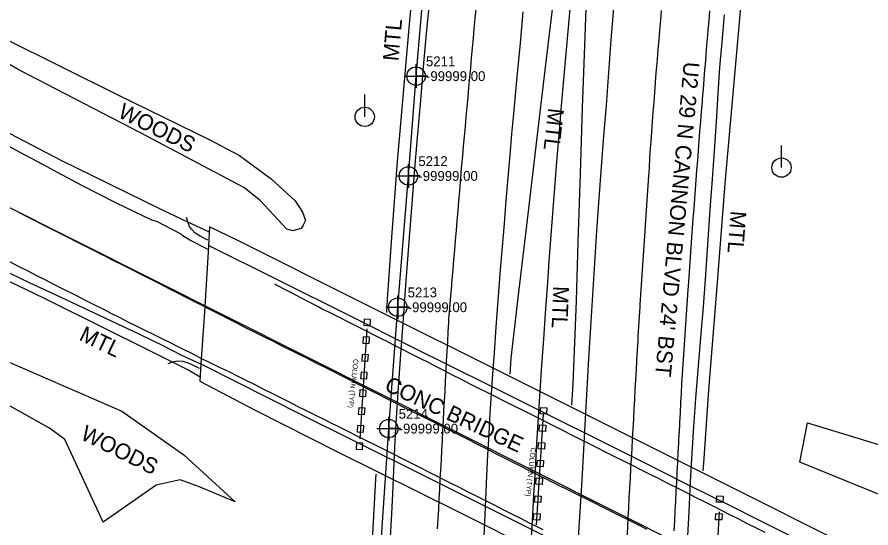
# Model space of a CAD drawing. Extents: x 1516784 to 1522736, y 634838 to 639369.
# Drawn here: x 1520333.6 to 1520550, y 638106.7 to 638236.3 of the extents above; entities that cross this region are included whole.
import ezdxf

# ---------------------------------------------------------------- set-up
doc = ezdxf.new("R2010")
doc.units = 0
for name, color, linetype in [('COGO Default Point Elevation', 7, 'Continuous'), ('COGO Default Point Number', 7, 'Continuous'), ('Exist Environmental Wetland Boundary Cogo Number', 7, 'Continuous'), ('Exist Environmental Wetland Boundary Text', 7, 'Continuous'), ('Exist Guardrail', 7, 'Continuous'), ('Exist Guardrail Text', 7, 'Continuous'), ('Exist Hydro Jurisdictional Stream or Body of Water NEU Mitigable', 7, 'Continuous'), ('Exist Hydro Swamp or Marsh Text', 7, 'Continuous'), ('Exist Roads EOT Text', 7, 'Continuous'), ('Exist Structure Major Deck Tunnel Box Culvert Text', 7, 'Continuous'), ('Exist Utilities Gas UG Line SUE LOS B', 7, 'Continuous'), ('Exist Utilities Gas UG Line SUE LOS B Cogo Elevation', 7, 'Continuous'), ('Exist Utilities Gas UG Line SUE LOS B Cogo Number', 7, 'Continuous'), ('Exist Utilities Gas UG Line SUE LOS B Cogo Point CELL', 7, 'Continuous'), ('Exist Utilities Power Pole CELL', 7, 'Continuous'), ('Exist Vegetation Woods Line', 7, 'Continuous'), ('Exist Vegetation Woods Line Text', 7, 'Continuous'), ('Scratch_Level_5', 7, 'Continuous')]:
    doc.layers.add(name, color=color, linetype=linetype)

msp = doc.modelspace()

# ---------------------------------------------------------------- linework, layer by layer
at = {"layer": 'COGO Default Point Elevation'}
for points in [[(1520449.83, 638238.35), (1520449.6, 638235.86), (1520449.38, 638233.37), (1520449.15, 638230.88), (1520448.92, 638228.39), (1520448.7, 638225.9), (1520448.47, 638223.42), (1520448.24, 638220.93), (1520448.02, 638218.44), (1520447.79, 638215.95), (1520447.56, 638213.46), (1520447.34, 638210.97), (1520447.11, 638208.49), (1520446.88, 638206), (1520446.66, 638203.51), (1520446.43, 638201.02), (1520446.37, 638200.42), (1520446.16, 638197.93), (1520445.95, 638195.44), (1520445.88, 638194.61), (1520445.67, 638192.12), (1520445.46, 638189.63), (1520445.26, 638187.14), (1520445.05, 638184.65), (1520444.84, 638182.16), (1520444.63, 638179.67), (1520444.42, 638177.18), (1520444.21, 638174.69), (1520444.01, 638172.21), (1520443.8, 638169.72), (1520443.59, 638167.23), (1520443.38, 638164.74), (1520443.17, 638162.25), (1520442.96, 638159.76), (1520442.89, 638158.92), (1520442.76, 638156.43), (1520442.63, 638153.93), (1520442.49, 638151.44), (1520442.36, 638148.94), (1520442.22, 638146.45), (1520442.09, 638143.96), (1520441.95, 638141.46), (1520441.82, 638138.97), (1520441.69, 638136.47), (1520441.55, 638133.98), (1520441.42, 638131.48), (1520441.28, 638128.99), (1520441.15, 638126.49), (1520441.02, 638124), (1520440.88, 638121.5), (1520440.75, 638119.01), (1520440.61, 638116.51), (1520440.48, 638114.02), (1520440.35, 638111.52), (1520440.21, 638109.03), (1520440.08, 638106.53)], [(1520488.18, 638104.39), (1520488.32, 638106.88), (1520488.45, 638109.38), (1520488.59, 638111.87), (1520488.73, 638114.37), (1520488.87, 638116.86), (1520489.01, 638119.35), (1520489.15, 638121.85), (1520489.28, 638124.34), (1520489.42, 638126.84), (1520489.56, 638129.33), (1520489.7, 638131.83), (1520489.84, 638134.32), (1520489.98, 638136.82), (1520490.11, 638139.31), (1520490.25, 638141.81), (1520490.39, 638144.3), (1520490.53, 638146.8), (1520490.67, 638149.29), (1520490.81, 638151.79), (1520490.94, 638154.28), (1520491, 638155.35), (1520491.16, 638157.84), (1520491.32, 638160.33), (1520491.48, 638162.83), (1520491.52, 638163.37), (1520491.68, 638165.86), (1520491.84, 638168.35), (1520492, 638170.84), (1520492.16, 638173.34), (1520492.32, 638175.83), (1520492.48, 638178.32), (1520492.64, 638180.82), (1520492.8, 638183.31), (1520492.81, 638183.51), (1520492.98, 638186.01), (1520493.15, 638188.5), (1520493.32, 638190.99), (1520493.49, 638193.48), (1520493.66, 638195.97), (1520493.81, 638198.05), (1520493.97, 638200.54), (1520494.14, 638203.04), (1520494.25, 638204.71), (1520494.44, 638207.2), (1520494.63, 638209.69), (1520494.82, 638212.19), (1520495.01, 638214.68), (1520495.2, 638217.17), (1520495.39, 638219.66), (1520495.58, 638222.15), (1520495.77, 638224.64), (1520495.84, 638225.5), (1520496.05, 638227.99), (1520496.27, 638230.48), (1520496.49, 638232.97), (1520496.7, 638235.46), (1520496.92, 638237.95)], [(1520500.14, 638106.03), (1520500.26, 638108.53), (1520500.38, 638111.02), (1520500.51, 638113.52), (1520500.62, 638115.86), (1520500.75, 638118.35), (1520500.88, 638120.85), (1520501.01, 638123.34), (1520501.14, 638125.84), (1520501.27, 638128.33), (1520501.4, 638130.83), (1520501.41, 638130.93), (1520501.54, 638133.43), (1520501.68, 638135.92), (1520501.82, 638138.42), (1520501.96, 638140.91), (1520502.08, 638143.25), (1520502.24, 638145.74), (1520502.4, 638148.24), (1520502.57, 638150.73), (1520502.73, 638153.22), (1520502.89, 638155.72), (1520502.98, 638157.12), (1520503.15, 638159.62), (1520503.32, 638162.11), (1520503.49, 638164.6), (1520503.66, 638167.09), (1520503.8, 638169.16), (1520503.97, 638171.65), (1520504.15, 638174.14), (1520504.32, 638176.63), (1520504.5, 638179.12), (1520504.67, 638181.62), (1520504.75, 638182.66), (1520504.94, 638185.16), (1520505.13, 638187.65), (1520505.32, 638190.14), (1520505.51, 638192.63), (1520505.69, 638194.93), (1520505.88, 638197.42), (1520506.06, 638199.91), (1520506.25, 638202.4), (1520506.44, 638204.83), (1520506.64, 638207.32), (1520506.84, 638209.81), (1520507.04, 638212.3), (1520507.24, 638214.79), (1520507.3, 638215.51), (1520507.5, 638218), (1520507.7, 638220.49), (1520507.91, 638222.98), (1520508, 638224.16), (1520508.21, 638226.65), (1520508.41, 638229.14), (1520508.62, 638231.63), (1520508.72, 638232.83), (1520508.94, 638235.32), (1520509.17, 638237.81)], [(1520381.04, 638162.84), (1520378.81, 638163.98), (1520376.59, 638165.12), (1520374.36, 638166.26), (1520372.14, 638167.4), (1520369.91, 638168.54), (1520368.97, 638169.02), (1520366.74, 638170.14), (1520364.51, 638171.27), (1520362.28, 638172.39), (1520360.05, 638173.52), (1520357.82, 638174.65), (1520355.58, 638175.77), (1520355.32, 638175.9), (1520353.09, 638177.04), (1520350.86, 638178.17), (1520348.63, 638179.3), (1520346.41, 638180.43), (1520344.18, 638181.56), (1520342.51, 638182.41), (1520340.28, 638183.54), (1520338.05, 638184.68), (1520335.83, 638185.81), (1520333.6, 638186.95)], [(1520331.66, 638174.25), (1520333.89, 638173.13), (1520334.09, 638173.02), (1520336.32, 638171.89), (1520338.55, 638170.76), (1520340.78, 638169.63), (1520343, 638168.49), (1520345.23, 638167.36), (1520347.46, 638166.23), (1520348.62, 638165.64), (1520350.85, 638164.51), (1520353.08, 638163.38), (1520355.31, 638162.26), (1520357.55, 638161.13), (1520359.78, 638160), (1520361.51, 638159.12), (1520363.75, 638158.01), (1520365.99, 638156.9), (1520368.23, 638155.79), (1520370.47, 638154.67), (1520372.71, 638153.56), (1520373.46, 638153.18), (1520375.7, 638152.06), (1520377.93, 638150.94), (1520379.97, 638149.9), (1520380.2, 638149.79)], [(1520398.79, 638168.61), (1520401.01, 638167.47), (1520403.23, 638166.32), (1520405.45, 638165.17), (1520407.67, 638164.02), (1520409.89, 638162.87), (1520410.95, 638162.32), (1520413.18, 638161.19), (1520415.41, 638160.06), (1520417.64, 638158.94), (1520419.87, 638157.81), (1520422.1, 638156.68), (1520424.33, 638155.55), (1520426.56, 638154.42), (1520426.76, 638154.32), (1520428.98, 638153.18), (1520431.21, 638152.05), (1520433.44, 638150.91), (1520435.67, 638149.78), (1520437.9, 638148.65), (1520439.25, 638147.96), (1520441.47, 638146.81), (1520443.69, 638145.67), (1520445.92, 638144.52), (1520448.14, 638143.38), (1520450.36, 638142.24), (1520452.6, 638141.13), (1520454.84, 638140.03), (1520457.08, 638138.92), (1520459.32, 638137.81), (1520461.56, 638136.71), (1520462.93, 638136.03), (1520465.16, 638134.9), (1520467.38, 638133.77), (1520469.61, 638132.64), (1520471.84, 638131.51), (1520474.07, 638130.38), (1520476.3, 638129.24), (1520478.3, 638128.23), (1520480.54, 638127.11), (1520482.77, 638125.98), (1520485.01, 638124.86), (1520487.24, 638123.74), (1520489.48, 638122.62), (1520491.71, 638121.5), (1520493.94, 638120.38), (1520496.18, 638119.26), (1520498.41, 638118.13), (1520498.77, 638117.96), (1520501, 638116.83), (1520503.23, 638115.7), (1520505.46, 638114.57), (1520507.69, 638113.44), (1520509.92, 638112.31), (1520512.15, 638111.18), (1520514.16, 638110.16), (1520516.39, 638109.03), (1520518.62, 638107.9), (1520520.86, 638106.77), (1520523.09, 638105.65)], [(1520493.23, 638106.38), (1520491, 638107.5), (1520488.76, 638108.62), (1520486.53, 638109.74), (1520484.29, 638110.86), (1520482.09, 638111.96), (1520479.85, 638113.08), (1520477.61, 638114.19), (1520475.38, 638115.3), (1520473.14, 638116.41), (1520470.9, 638117.53), (1520468.66, 638118.64), (1520467.9, 638119.02), (1520465.66, 638120.14), (1520463.42, 638121.25), (1520461.19, 638122.37), (1520458.95, 638123.49), (1520457.15, 638124.4), (1520454.92, 638125.54), (1520452.7, 638126.68), (1520450.47, 638127.82), (1520448.25, 638128.96), (1520446.02, 638130.1), (1520444.49, 638130.88), (1520442.26, 638131.99), (1520440.02, 638133.11), (1520437.78, 638134.22), (1520435.54, 638135.33), (1520433.3, 638136.44), (1520431.73, 638137.22), (1520429.51, 638138.35), (1520427.28, 638139.49), (1520425.05, 638140.62), (1520422.82, 638141.76), (1520420.6, 638142.89), (1520418.37, 638144.03), (1520418.19, 638144.12), (1520415.95, 638145.25), (1520413.72, 638146.37), (1520411.49, 638147.5), (1520409.26, 638148.62), (1520407.02, 638149.75), (1520405.26, 638150.64), (1520403.02, 638151.75), (1520400.78, 638152.86), (1520398.54, 638153.97), (1520396.3, 638155.08), (1520394.06, 638156.19), (1520393.9, 638156.27), (1520391.67, 638157.41), (1520389.45, 638158.55), (1520387.22, 638159.68), (1520384.99, 638160.82), (1520382.77, 638161.95), (1520381.92, 638162.39), (1520381.37, 638162.67)], [(1520380.33, 638149.73), (1520382.58, 638148.64), (1520384.83, 638147.54), (1520387.08, 638146.45), (1520389.37, 638145.33), (1520391.6, 638144.21), (1520393.83, 638143.08), (1520396.07, 638141.96), (1520398.3, 638140.83), (1520400.53, 638139.7), (1520402.54, 638138.69), (1520404.77, 638137.57), (1520407, 638136.45), (1520409.24, 638135.33), (1520411.47, 638134.21), (1520412.95, 638133.47), (1520415.19, 638132.36), (1520417.43, 638131.24), (1520419.67, 638130.13), (1520421.91, 638129.02), (1520424.15, 638127.91), (1520426.39, 638126.8), (1520426.68, 638126.65), (1520428.91, 638125.52), (1520431.14, 638124.39), (1520433.37, 638123.25), (1520435.6, 638122.12), (1520437.83, 638120.99), (1520440.06, 638119.86), (1520441.31, 638119.22), (1520443.54, 638118.09), (1520445.77, 638116.97), (1520448, 638115.84), (1520450.23, 638114.71), (1520452.47, 638113.59), (1520454.45, 638112.59), (1520456.68, 638111.46), (1520458.91, 638110.33), (1520461.14, 638109.2), (1520463.37, 638108.08), (1520465.6, 638106.95), (1520466.79, 638106.35)]]:
    msp.add_lwpolyline(points, dxfattribs=at)
at = {"layer": 'COGO Default Point Number'}
for points in [[(1520438.23, 638241.19), (1520437.37, 638233.01), (1520436.59, 638224.54), (1520435.8, 638215.21), (1520434.97, 638205.7), (1520434.29, 638197.75), (1520433.59, 638189.02), (1520432.85, 638179.26), (1520432.13, 638169.41), (1520431.45, 638159.85), (1520430.79, 638150.79), (1520430.09, 638141.17), (1520429.74, 638135.92), (1520429.41, 638130.44), (1520429.16, 638125.27), (1520428.74, 638115.49), (1520428.46, 638110.31), (1520428.17, 638104.52)], [(1520475.78, 638102.87), (1520476.3, 638110.91), (1520476.78, 638118.82), (1520477.22, 638126.67), (1520477.63, 638134.41), (1520478.05, 638142.02), (1520478.49, 638149.69), (1520478.97, 638157.62), (1520479.48, 638165.73), (1520480, 638173.89), (1520480.54, 638182.08), (1520481.12, 638190.25), (1520481.72, 638198.29), (1520482.32, 638206.09), (1520482.92, 638213.95), (1520483.52, 638222.19), (1520484.15, 638230.47), (1520484.83, 638238.5)], [(1520461.77, 638237.59), (1520461.05, 638229.63), (1520460.26, 638221.07), (1520459.39, 638211.75), (1520458.92, 638206.67), (1520458.45, 638201.28), (1520457.97, 638195.59), (1520457.48, 638189.74), (1520456.99, 638183.89), (1520456.52, 638178.03), (1520456.05, 638172.16), (1520455.61, 638166.63), (1520454.92, 638157.67), (1520454.46, 638151.22), (1520454.08, 638145.76), (1520453.43, 638135.88), (1520453.11, 638130.61), (1520452.81, 638125.29), (1520452.53, 638119.98), (1520452.13, 638110.07), (1520451.75, 638102.73)], [(1520503.47, 638103.1), (1520503.89, 638110.83), (1520504.28, 638118.45), (1520504.66, 638125.74), (1520505.08, 638132.5), (1520505.59, 638139.58), (1520506.24, 638147.85), (1520506.92, 638156.01), (1520507.49, 638162.78), (1520508.04, 638169.75), (1520508.64, 638178.5), (1520509.24, 638187.49), (1520509.79, 638195.14), (1520510.3, 638202.27), (1520510.79, 638209.66), (1520511.25, 638216.87), (1520511.71, 638223.44), (1520512.24, 638229.9), (1520512.89, 638236.8)], [(1520381.99, 638177.31), (1520377.41, 638179.72), (1520375.6, 638180.76), (1520375.46, 638180.91), (1520375.37, 638181.04), (1520375.17, 638181.2), (1520373.1, 638182.35), (1520369.03, 638184.43), (1520368.45, 638184.64), (1520368.13, 638184.67), (1520367.59, 638184.81), (1520358.82, 638189.08), (1520350.02, 638193.59), (1520343.98, 638196.76), (1520340.09, 638198.87), (1520334.39, 638201.95), (1520327.44, 638205.67)], [(1520329.3, 638172.52), (1520336.65, 638168.99), (1520343.4, 638165.85), (1520350.25, 638162.63), (1520359.04, 638158.48), (1520364.63, 638155.89), (1520370.56, 638152.96), (1520375.13, 638150.62), (1520376.39, 638150.04), (1520380.07, 638148.38)]]:
    msp.add_lwpolyline(points, dxfattribs=at)
at = {"layer": 'Exist Environmental Wetland Boundary Cogo Number'}
for points in [[(1520381.94, 638179.67), (1520380.03, 638180.69), (1520378.73, 638181.51), (1520377.83, 638182.45), (1520377.33, 638183.2), (1520376.92, 638184.16), (1520376.55, 638185.46)], [(1520379.85, 638147.17), (1520377.49, 638148.35), (1520375.73, 638148.94), (1520374.32, 638149.04), (1520372.94, 638148.78), (1520371.77, 638148.38)]]:
    msp.add_lwpolyline(points, dxfattribs=at)
at = {"layer": 'Exist Environmental Wetland Boundary Text'}
msp.add_line((1519517.96, 638596.36), (1520558.73, 638073.97), dxfattribs=at)
msp.add_arc((1524058.56, 637908.82), 3600, 171.45942, 178.18867, dxfattribs=at)
at = {"layer": 'Exist Guardrail'}
for points in [[(1520428.5, 638179.26), (1520430, 638199.66), (1520431.32, 638215.05), (1520432.57, 638228.67), (1520434.06, 638245.7), (1520435.81, 638266.83), (1520437.44, 638285.13), (1520438.58, 638299.42)], [(1520520.76, 638280.71), (1520519.06, 638262.19), (1520517.13, 638241.62), (1520515.12, 638218.71), (1520512.96, 638194.07), (1520510.99, 638169), (1520508.82, 638141.65), (1520507.49, 638123.17), (1520507.38, 638121.26)], [(1520471.48, 638257.31), (1520468.98, 638236.84), (1520467.73, 638226.37), (1520466.09, 638212.12), (1520462.71, 638183.41), (1520460.64, 638166.51), (1520458.72, 638149.82), (1520458.46, 638145.77)], [(1520474.21, 638137.88), (1520474.52, 638143.31), (1520475.32, 638164.35), (1520475.79, 638179.26), (1520476.39, 638196.55), (1520476.9, 638213.25), (1520477.52, 638231.26), (1520478.1, 638248.34), (1520478.12, 638249.07)], [(1520300.89, 638223.83), (1520316.04, 638215.31), (1520329.84, 638207.76), (1520344.86, 638199.92), (1520352.65, 638196.09), (1520370.24, 638187.51), (1520375.51, 638184.91), (1520382.29, 638181.85)], [(1520380.03, 638145), (1520376.86, 638146.82), (1520372.49, 638149.01), (1520365.53, 638152.48), (1520356.51, 638156.93), (1520340.55, 638164.88), (1520322.59, 638173.56), (1520311.53, 638178.87), (1520298.83, 638185.03)], [(1520427.28, 638161.4), (1520427.49, 638164.71), (1520428.5, 638179.26)], [(1520420.78, 638046.39), (1520422, 638071.03), (1520423.19, 638094.31), (1520424.48, 638119.09), (1520424.56, 638120.37)]]:
    msp.add_lwpolyline(points, dxfattribs=at)
at = {"layer": 'Exist Hydro Jurisdictional Stream or Body of Water NEU Mitigable'}
for p, q in [((1520465.18, 638107.5), (1520466.97, 638135.52)), ((1520511.54, 638110.79), (1520509.87, 638084.86))]:
    msp.add_line(p, q, dxfattribs=at)
msp.add_lwpolyline([(1520422.21, 638157.2), (1520420.42, 638129.37)], dxfattribs=at)
at = {"layer": 'Exist Hydro Swamp or Marsh Text'}
for points in [[(1520551.82, 638093.57), (1520551.79, 638097.59), (1520542.8, 638102.87), (1520514.84, 638116.88), (1520462.99, 638142.85), (1520418.16, 638165.28), (1520392.4, 638178.2), (1520389.54, 638179.58), (1520382.4, 638183.11), (1520382.11, 638178.37)], [(1520545.94, 638096.51), (1520520.36, 638109.3), (1520515.36, 638111.83), (1520504.08, 638117.46), (1520491.92, 638123.56), (1520481.28, 638128.89), (1520468.88, 638135.11), (1520453.33, 638142.88), (1520433.91, 638152.5), (1520417.78, 638160.63), (1520382.11, 638178.37), (1520382, 638176.72), (1520381.06, 638161.53), (1520380.17, 638148.33), (1520406.27, 638135.2), (1520418.02, 638129.31), (1520438.38, 638119.16), (1520460.49, 638108.14), (1520475.44, 638100.62)], [(1520380.17, 638148.33), (1520379.88, 638143.99), (1520393.93, 638136.59), (1520414.99, 638125.99), (1520445.27, 638110.89), (1520484.97, 638090.98), (1520508.76, 638079.01), (1520537.87, 638064.33), (1520549.6, 638059.06), (1520549.88, 638063.3)]]:
    msp.add_lwpolyline(points, dxfattribs=at)
at = {"layer": 'Exist Utilities Gas UG Line SUE LOS B'}
msp.add_lwpolyline([(1520421.99, 638012.85), (1520423.24, 638041.59), (1520424.56, 638071.73), (1520425.71, 638100.61), (1520427.79, 638131.93), (1520430.07, 638162.7), (1520432.78, 638195.98), (1520434.71, 638221.28), (1520437.33, 638251.93), (1520440.16, 638282.54), (1520443.58, 638313.36), (1520448.01, 638349.54), (1520452.24, 638384.87), (1520455.33, 638410.59), (1520458.64, 638433.49), (1520462.73, 638460.82), (1520469.03, 638500.18), (1520473.79, 638526.76), (1520479.12, 638557.52), (1520484.57, 638589.44), (1520490.16, 638619.21)], dxfattribs=at)
at = {"layer": 'Exist Utilities Gas UG Line SUE LOS B Cogo Point CELL'}
for points in [[(1520431.71, 638221.28), (1520437.71, 638221.28), (1520434.71, 638221.28), (1520434.71, 638224.28), (1520434.71, 638218.28)], [(1520429.78, 638195.98), (1520435.78, 638195.98), (1520432.78, 638195.98), (1520432.78, 638198.98), (1520432.78, 638192.98)], [(1520427.07, 638162.7), (1520433.07, 638162.7), (1520430.07, 638162.7), (1520430.07, 638165.7), (1520430.07, 638159.7)], [(1520424.79, 638131.93), (1520430.79, 638131.93), (1520427.79, 638131.93), (1520427.79, 638134.93), (1520427.79, 638128.93)]]:
    msp.add_lwpolyline(points, dxfattribs=at)
for centre in [(1520434.71, 638221.28), (1520432.78, 638195.98), (1520430.07, 638162.7), (1520427.79, 638131.93)]:
    msp.add_circle(centre, 2.34, dxfattribs=at)
at = {"layer": 'Exist Utilities Power Pole CELL'}
for p, q in [((1520421.7, 638210.96), (1520421.7, 638216.59)), ((1520421.7, 638210.96), (1520421.7, 638210.96)), ((1520527.29, 638198.09), (1520527.29, 638203.72)), ((1520527.29, 638198.09), (1520527.29, 638198.09))]:
    msp.add_line(p, q, dxfattribs=at)
for centre in [(1520421.7, 638210.96), (1520527.29, 638198.09)]:
    msp.add_circle(centre, 2.45, dxfattribs=at)
at = {"layer": 'Exist Vegetation Woods Line'}
for points in [[(1520401.95, 638182.52), (1520395.21, 638189.74), (1520391.1, 638193.02), (1520364.92, 638206.92), (1520333.84, 638222.96), (1520318.33, 638231.91), (1520314.74, 638234.59), (1520313.85, 638237.36), (1520316.1, 638237.89), (1520358.94, 638216.59), (1520382.44, 638205.17), (1520389.99, 638201.12), (1520398, 638195.21), (1520404.09, 638189.64), (1520405.94, 638186.8), (1520406.66, 638184.65), (1520406.06, 638183.53), (1520405.56, 638182.69), (1520403.49, 638182.05), (1520401.95, 638182.52)], [(1520327.08, 638150.74), (1520360.14, 638136.39), (1520375.82, 638125.32), (1520388.87, 638113.35)], [(1520388.87, 638113.35), (1520379.61, 638117.28), (1520374.92, 638118.9), (1520368.86, 638117.57), (1520355.38, 638108.25), (1520345.69, 638129.17), (1520341.85, 638132.03), (1520311.25, 638149.11)], [(1520559.71, 638112.1), (1520531.98, 638123.41), (1520533.92, 638133.39), (1520555.77, 638126.72)]]:
    msp.add_lwpolyline(points, dxfattribs=at)
at = {"layer": 'Scratch_Level_5'}
for points in [[(1520421.56, 638159.7), (1520421.45, 638158.11), (1520423.05, 638158.02), (1520423.16, 638159.61)], [(1520421.3, 638155.22), (1520421.19, 638153.62), (1520422.79, 638153.54), (1520422.89, 638155.13)], [(1520421.02, 638150.74), (1520420.92, 638149.14), (1520422.51, 638149.06), (1520422.62, 638150.65)], [(1520420.75, 638146.21), (1520420.64, 638144.62), (1520422.24, 638144.53), (1520422.34, 638146.13)], [(1520420.47, 638141.72), (1520420.36, 638140.12), (1520421.96, 638140.03), (1520422.07, 638141.63)], [(1520420.18, 638137.21), (1520420.07, 638135.61), (1520421.67, 638135.52), (1520421.78, 638137.12)], [(1520467.78, 638135.6), (1520466.18, 638135.71), (1520466.28, 638137.31), (1520467.87, 638137.2)], [(1520419.9, 638132.73), (1520419.79, 638131.13), (1520421.39, 638131.04), (1520421.5, 638132.64)], [(1520467.51, 638131.17), (1520465.91, 638131.28), (1520466, 638132.88), (1520467.6, 638132.77)], [(1520419.63, 638128.31), (1520419.52, 638126.71), (1520421.12, 638126.62), (1520421.23, 638128.22)], [(1520467.22, 638126.68), (1520465.62, 638126.79), (1520465.72, 638128.39), (1520467.31, 638128.28)], [(1520466.93, 638122.23), (1520465.34, 638122.34), (1520465.43, 638123.94), (1520467.03, 638123.83)], [(1520466.64, 638117.73), (1520465.04, 638117.84), (1520465.14, 638119.43), (1520466.73, 638119.33)], [(1520466.35, 638113.19), (1520464.75, 638113.3), (1520464.84, 638114.9), (1520466.44, 638114.79)], [(1520512.42, 638113.24), (1520510.82, 638113.32), (1520510.91, 638114.92), (1520512.5, 638114.84)], [(1520466.07, 638108.71), (1520464.47, 638108.81), (1520464.57, 638110.41), (1520466.16, 638110.3)], [(1520512.15, 638108.76), (1520510.55, 638108.84), (1520510.64, 638110.44), (1520512.24, 638110.35)]]:
    msp.add_lwpolyline(points, close=True, dxfattribs=at)

# ---------------------------------------------------------------- texts
at = {"layer": 'Exist Guardrail Text'}
for rotation, p in [(85.001, (1520430.24, 638224.99)), (263.2923, (1520468.24, 638213.34)), (265.5078, (1520514.43, 638187.23)), (267.8226, (1520469.46, 638168.11)), (334.3625, (1520349.08, 638154.47))]:
    msp.add_text('MTL', height=4, rotation=rotation, dxfattribs=at).set_placement(p)
at = {"layer": 'Exist Roads EOT Text'}
msp.add_text("U2 29 N CANNON BLVD 24' BST", height=4, rotation=264.7681, dxfattribs=at).set_placement((1520502.57, 638225.04))
at = {"layer": 'Exist Structure Major Deck Tunnel Box Culvert Text'}
msp.add_text('CONC BRIDGE', height=4, rotation=334.9664, dxfattribs=at).set_placement((1520426.43, 638141.72))
at = {"layer": 'Exist Utilities Gas UG Line SUE LOS B Cogo Elevation'}
for p in [(1520437.21, 638220.03), (1520435.28, 638194.73), (1520432.57, 638161.45), (1520430.29, 638130.68)]:
    msp.add_text('-99999.00', height=2.5, dxfattribs=at).set_placement(p)
at = {"layer": 'Exist Utilities Gas UG Line SUE LOS B Cogo Number'}
for s, p in [('5211', (1520437.21, 638223.78)), ('5212', (1520435.28, 638198.48)), ('5213', (1520432.57, 638165.2)), ('5214', (1520430.29, 638134.43))]:
    msp.add_text(s, height=2.5, dxfattribs=at).set_placement(p)
at = {"layer": 'Exist Vegetation Woods Line Text'}
for p in [(1520358.89, 638211.01), (1520349.42, 638129.39)]:
    msp.add_text('WOODS', height=4, rotation=333.5021, dxfattribs=at).set_placement(p)
at = {"layer": 'Scratch_Level_5'}
for p in [(1520418.88, 638149.62), (1520463.82, 638127.16)]:
    msp.add_text('COLUMN (TYP)', height=1.25, rotation=263.6337, dxfattribs=at).set_placement(p)

doc.saveas('drawing.dxf')
